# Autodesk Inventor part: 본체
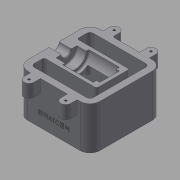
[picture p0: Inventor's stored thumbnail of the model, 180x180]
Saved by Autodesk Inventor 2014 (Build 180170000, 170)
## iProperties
Created: 2018-01
Part Number: 본체
Material: Generic
Document SubType Name: Modeling
Designer: user
Density: 1 g/cm^3
Appearance: Default
Author: user
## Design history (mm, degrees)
sketch "스케치2"
  geometry: L1 (-55, -55)-(55, -55); L2 (55, -55)-(55, 55); L3 (55, 55)-(-55, 55); L4 (-55, 55)-(-55, -55); L5 (-55, -55)-(55, 55); L6 (55, -55)-(-55, 55); 3 further points
  constraints: 12 end point, 3 midpoint, 2 parallel, 1 coincident, 1 horizontal, 1 perpendicular
  dimensions: "d2" = 110 distance of L2.end L3.end; "d3" = 110 distance of L1.end L2.end
extrude "돌출1" new body sketch "스케치2" stored distance "d4" = 65; taper "d5" = 0 deg
fillet "모깎기1" dims "d6" = 15
sketch "스케치3"
  geometry: L1 (40, 55)-(-40, 55) reference; L2 (-55, 40)-(-55, -40) reference; L3 (-40, -55)-(40, -55) reference; L4 (55, -40)-(55, 40) reference; L5 (-40, 45)-(40, 45); L6 (45, 40)-(45, -40); L7 (40, -45)-(-40, -45); L8 (-45, 25)-(-45, 40); L9 (0, 25)-(0, -25); L10 (-45, -25)-(-45, -40); L11 (-45, 25)-(32, 25); L12 (35, 22)-(35, -22); L13 (-45, -25)-(32, -25); A1 r 15 centre (40, 40) between (55, 40) and (40, 55) reference; A2 r 15 centre (-40, 40) between (-40, 55) and (-55, 40) reference; A3 r 15 centre (-40, -40) between (-55, -40) and (-40, -55) reference; A4 r 15 centre (40, -40) between (40, -55) and (55, -40) reference; A5 r 5 centre (40, 40) between (45, 40) and (40, 45); A6 r 5 centre (40, -40) between (40, -45) and (45, -40); A7 r 5 centre (-40, -40) between (-45, -40) and (-40, -45); A8 r 5 centre (-40, 40) between (-40, 45) and (-45, 40); A9 r 3 centre (32, 22) between (35, 22) and (32, 25); A10 r 3 centre (32, -22) between (32, -25) and (35, -22); 2 further points
  constraints: 18 end point, 12 point on circle, 6 centre point, 5 tangent, 3 perpendicular, 2 point on line, 1 coincident, 1 equal radius, 1 horizontal alignment, 1 midpoint, 1 parallel, 7 other
  dimensions: "d7" = 10 distance between parallel lines of L1 L5; "d8" = 50 distance of L9.start L9.end; "d66" = 20 distance between parallel lines of L12 L4; "d67" = 3 radius of A9
extrude "돌출2" cut sketch "스케치3" stored distance "d13" = 95.3375; taper "d14" = 0 deg
sketch "스케치4"
  geometry: L1 (-55, 32.5)-(-40, 32.5) reference; L2 (-55, 32.5)-(30, 32.5); L3 (30, 32.5)-(30, 46.5); L4 (29, 47.5)-(25, 47.5); L5 (25, 47.5)-(25, 51.5); L6 (24, 52.5)-(-21, 52.5); L7 (-22, 51.5)-(-22, 48.5); L8 (-22, 48.5)-(-35, 48.5); L9 (-36, 47.5)-(-36, 40); L10 (-36, 40)-(-55, 40); L11 (-55, 40)-(-55, 32.5); A1 r 1 centre (-35, 47.5) between (-35, 48.5) and (-36, 47.5); A2 r 1 centre (-21, 51.5) between (-21, 52.5) and (-22, 51.5); A3 r 1 centre (24, 51.5) between (25, 51.5) and (24, 52.5); A4 r 1 centre (29, 46.5) between (30, 46.5) and (29, 47.5); 5 further points
  constraints: 20 end point, 8 point on circle, 8 point on line, 8 tangent, 7 parallel, 4 centre point, 3 equal radius, 2 perpendicular, 1 collinear
  dimensions: "d15" = 85 distance of L1.start L2.end; "d16" = 15 diameter of L10 L2; "d17" = 32 diameter of L8 L2; "d18" = 40 diameter of L6 L2; "d19" = 30 diameter of L4 L2; "d20" = 5 distance of point (30, 47.5) L4.end; "d21" = 47 distance of point (25, 52.5) point (-22, 52.5); "d22" = 14 distance of L7.end point (-36, 48.5); "d23" = 1 radius of A1
revolve "회전1" sketch "스케치4" stored, may be unused: angle "d24" = 90 deg
chamfer "모따기1" distance "d25" = 1; stored, may be unused: second distance "d26" = 2, angle "d27" = 45 deg
sketch "스케치5"
  geometry: L1 (40, 55)-(-40, 55) reference; L2 (-55, 40)-(-55, 8.5) reference; L3 (-20.5, 65)-(-20.5, 55); L4 (-35.5, 65)-(-35.5, 55); A1 r 7.5 centre (-28, 65) between (-20.5, 65) and (-35.5, 65); 1 further point
  constraints: 4 end point, 2 perpendicular, 2 point on circle, 2 point on line, 2 tangent, 1 centre point
  dimensions: "d28" = 15 diameter of A1; "d29" = 27 distance from line of A1.centre L2; "d30" = 10 distance from line of L1 A1.centre
extrude "돌출3" join sketch "스케치5" distance "d31" = 20; taper "d32" = 0 deg
fillet "모깎기2" dims "d33" = 3
hole "구멍1" diameter "d36" = 3.242; stored, may be unused: countersink angle "d40" = 90 deg, drill point angle "d42" = 118 deg; dims "d34" = 10, "d35" = 10, "d37" = 9, "d38" = 4, "d39" = 2, "d41" = 11
sketch "스케치6"
  geometry: L1 (0, 65)-(31.5, 65) reference; L2 (0, 0)-(0, 65) reference; L3 (80, 0)-(0, 0) reference; L4 (80, 65)-(80, 0) reference; L5 (48.5, 65)-(80, 65) reference; L6 (24.96, 11)-(54.96, 11); L7 (54.96, 11)-(54.96, 29) reference; L8 (54.96, 29)-(24.96, 29); L9 (24.96, 29)-(24.96, 11); L10 (24.96, 11)-(54.96, 29); L11 (54.96, 11)-(24.96, 29); A1 r 8.5 centre (40, 65) between (31.5, 65) and (48.5, 65) reference; 2 further points
  constraints: 12 end point, 2 midpoint, 2 parallel, 1 horizontal, 1 perpendicular, 1 vertical
  dimensions: "d46" = 30 distance of L7.end L8.end; "d47" = 18 distance of L6.end L7.end; "d48" = 20 distance from line of L3 point (39.96, 20)
sketch "스케치7"
  geometry: L1 (-17, 6.682)-(-55, -3.5); L2 (-55, -21.5)-(-55, -3.5) reference; L3 (-55, -21.5)-(20, -2.5); L4 (-17, 17.643)-(20, 17.643) reference; L5 (20, 17.643)-(20, -2.5); L6 (-17, 6.682)-(-17, 17.643); L7 (24, 12.5)-(-21, 12.5) reference; L8 (-55, -3.5)-(-55, -21.5); 5 further points
  constraints: 12 end point, 2 horizontal, 2 midpoint, 1 collinear, 1 parallel, 1 perpendicular, 1 point on line, 1 vertical alignment
  dimensions: "d51" = 75 deg angle of L2 L1; "d54" = 37 distance of L4.start L4.end; "d58" = 30 vertical distance of point (35, -32.5) L3.end
extrude "돌출4" cut sketch "스케치7" stored distance "d55" = 30; taper "d56" = 0 deg
fillet "모깎기3" dims "d57" = 3
sketch "스케치10"
  geometry: L1 (45, 32.5)-(45, -32.5) reference; L2 (35, 32.5)-(35, -32.5) reference; L3 (-45, 32.5)-(-45, -32.5) reference; L4 (45, -32.5)-(-45, -32.5); L5 (-42.776, -23.34)-(32.776, -3.096); L6 (-45, -26.238)-(-45, -32.5); L7 (35, -0.198)-(35, 32.5); L8 (45, 32.5)-(35, 32.5); L9 (45, 32.5)-(45, -32.5); A1 r 3 centre (-42, -26.238) between (-42.776, -23.34) and (-45, -26.238); A2 r 3 centre (32, -0.198) between (32.776, -3.096) and (35, -0.198); 3 further points
  constraints: 12 end point, 6 point on line, 4 point on circle, 4 tangent, 3 collinear, 2 centre point, 2 perpendicular, 1 equal radius
  dimensions: "d68" = 105 deg angle of L5 L3; "d69" = 30 distance from line of L4 point (35, -2.5); "d70" = 3 radius of A1
extrude "돌출6" cut sketch "스케치10" stored distance "d71" = 60; taper "d72" = 0 deg
fillet "모깎기4" dims "d73" = 3
sketch "스케치11"
  geometry: L1 (80, 0)-(0, 0) reference; L2 (-15, 65)-(-15, 0) reference; 2 further points
  constraints: 1 other
  dimensions: "d74" = 55 distance from line of L2 point (40, 20); "d75" = 20 distance from line of L1 point (40, 20)
extrude "돌출7" join sketch "스케치11" distance "d76" = 0.5; taper "d77" = 0 deg
node "솔리드1"
pattern_linear "직사각형 패턴1" dims "d45" = 56
mirror "대칭1"
